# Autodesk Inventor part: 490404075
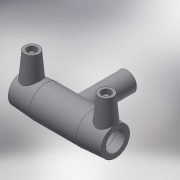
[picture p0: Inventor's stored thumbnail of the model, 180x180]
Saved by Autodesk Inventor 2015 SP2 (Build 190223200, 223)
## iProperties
Created: 2017-06
Part Number: 490404075
Material: Generic
Description: PLASSON TEE 75-75-75
Document SubType Name: Modeling
Designer: KIM
Mass: 57.3761 g
Surface Area: 241.06 cm^2
Volume: 57.3761 cm^3
Density: 1 g/cm^3
Appearance: Default
Author: KIM
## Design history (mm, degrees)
derived "490404.ipt"
feature "Solid1::490404.ipt"
tag "TaggingFeature1"
body "Solid1"
other parameters: "d0" = 196, "d1" = 75, "d2" = 96, "d3" = 63, "d4" = 49, "d5" = 86.4, "d6" = 71.25, "d7" = 75, "d8" = 168 deg, "d10" = 25.2, "d11" = 8.4, "d13" = 196, "d14" = 17.6296, "d17" = 67.5, "d18" = 75, "d19" = 3.52592, "d20" = 168 deg, "d22" = 89.28, "d23" = 96, "d24" = 86.6016, "d25" = 135 deg, "d26" = 137.2, "d27" = 135 deg, "d29" = 62, "d30" = 15, "d31" = 78.4, "d34" = 5 deg, "d35" = 15, "d39" = 5 deg, "d40" = 9.6, "d41" = 4.8, "d42" = 6, "d43" = 0, "d45" = 4, "d46" = 14, "d47" = 0, "d48" = -129, "d49" = 75, "d51" = 0, "d54" = 0, "d55" = 86.4, "d56" = 96, "d57" = 68.6, "d58" = 135 deg, "d59" = 63, "d60" = 63, "d61" = 135 deg, "d62" = 129, "d72" = 89.18, "d73" = 44.59, "d74" = -129, "d75" = 78.75, "d77" = 0, "d80" = 0, "d81" = 75, "d82" = 81, "d83" = 0, "d84" = 3, "d85" = 0, "d86" = 3, "d87" = 0, "d88" = 18.27, "d89" = 4.5675, "d90" = 18.27, "d_" = 75, "L_" = 196, "L_1" = 63, "D_" = 96, "A_" = 62, "d_2" = 12, "H_" = 129
